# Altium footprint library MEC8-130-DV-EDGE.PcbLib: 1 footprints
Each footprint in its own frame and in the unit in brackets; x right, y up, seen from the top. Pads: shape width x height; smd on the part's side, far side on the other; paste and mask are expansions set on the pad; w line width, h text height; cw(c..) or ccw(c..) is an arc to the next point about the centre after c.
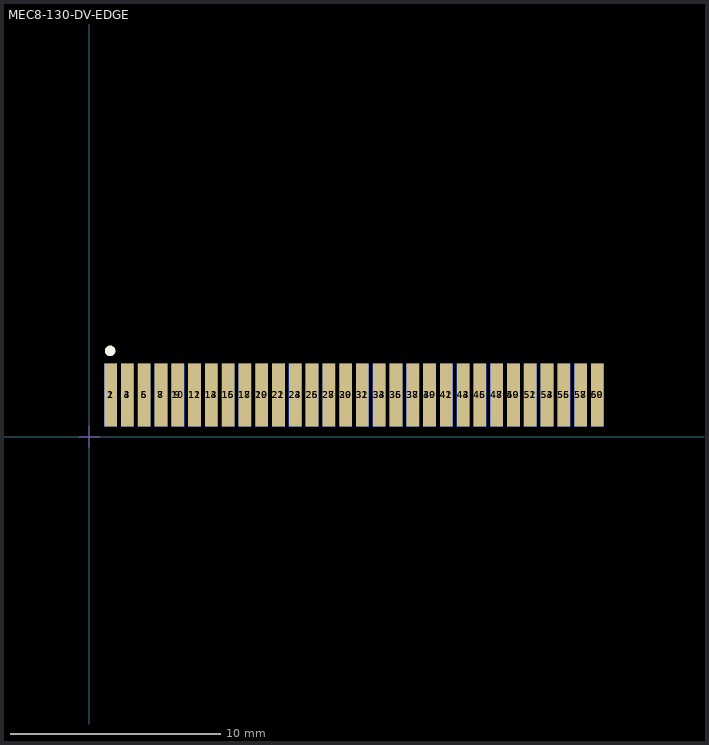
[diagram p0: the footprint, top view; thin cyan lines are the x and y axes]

## MEC8-130-DV-EDGE [mm] "edge card; mates w/MEC8-130-XX-XX-DV"
height 8.65
pads (60):
  rect 0.6x3 smd: 1(1.025,2) 3(1.825,2) 5(2.625,2) 7(3.425,2) 9(4.225,2) 11(5.025,2) 13(5.825,2) 15(6.625,2) 17(7.425,2) 19(8.225,2) 21(9.025,2) 23(9.825,2) 25(10.625,2) 27(11.425,2) 29(12.225,2) 31(13.025,2) 33(13.825,2) 35(14.625,2) 37(15.425,2) 39(16.225,2) 41(17.025,2) 43(17.825,2) 45(18.625,2) 47(19.425,2) 49(20.225,2) 51(21.025,2) 53(21.825,2) 55(22.625,2) 57(23.425,2) 59(24.225,2)
  rect 0.6x3 smd far side: 2(1.025,2) 4(1.825,2) 6(2.625,2) 8(3.425,2) 10(4.225,2) 12(5.025,2) 14(5.825,2) 16(6.625,2) 18(7.425,2) 20(8.225,2) 22(9.025,2) 24(9.825,2) 26(10.625,2) 28(11.425,2) 30(12.225,2) 32(13.025,2) 34(13.825,2) 36(14.625,2) 38(15.425,2) 40(16.225,2) 42(17.025,2) 44(17.825,2) 46(18.625,2) 48(19.425,2) 50(20.225,2) 52(21.025,2) 54(21.825,2) 56(22.625,2) 58(23.425,2) 60(24.225,2)
Top Overlay:
  circle w0.25: c1,4.1 r0.125
Top Solder:
  region: -0.1,-0.1 25.4,-0.1 25.4,3.6 -0.1,3.6
Bottom Solder:
  region: 25.4,3.6 -0.1,3.6 -0.1,-0.1 25.4,-0.1
Mechanical 13:
  text ".Designator" at 0.254,0.254 h1.52
Mechanical 15:
  lines w0.05: -0.5,0 0.5,0 ; 0,-0.5 0,0.5
Drill Drawing:
  lines w0.01: -2.54,6.5 -1.2,6.5 cw(c-1.2,5.3) 0,5.3 0,0 25.25,0 25.25,5.3 cw(c26.45,5.3) 26.45,6.5 27.79,6.5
